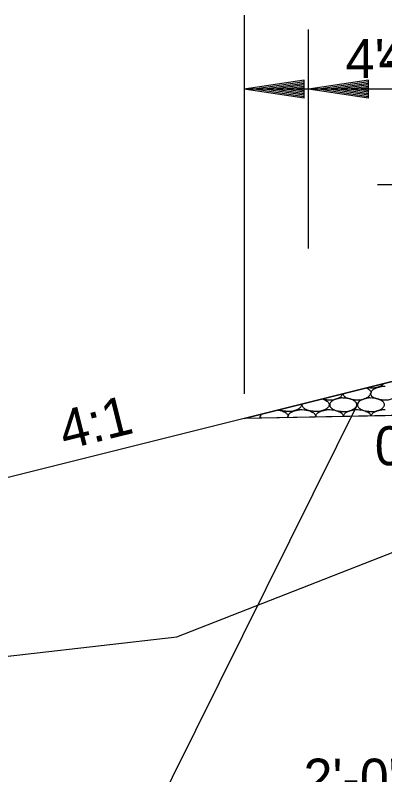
# Model space of a CAD drawing. Extents: x 1373719 to 1374161, y 379835 to 380167.
# Drawn here: x 1373940.76 to 1373946.92, y 380106.35 to 380119.01 of the extents above; entities that cross this region are included whole.
import ezdxf

# ---------------------------------------------------------------- set-up
doc = ezdxf.new("R2010")
doc.units = 0
for name, color, linetype in [('Agg Base Course Text', 7, 'Continuous'), ('Aggregate Base Course', 7, 'Continuous'), ('GREEN_TXT', 7, 'Continuous'), ('SIGNATURE', 7, 'Continuous'), ('T_Drafting', 7, 'Continuous'), ('Text 1', 7, 'Continuous')]:
    doc.layers.add(name, color=color, linetype=linetype)

msp = doc.modelspace()

# ---------------------------------------------------------------- linework, layer by layer
for p, q in [((1373950.023, 380113.65), (1373934.02, 380109.65)), ((1373955.044, 380112.497), (1373944.572, 380112.288))]:
    msp.add_line(p, q)
at = {"layer": 'Agg Base Course Text'}
msp.add_lwpolyline([(1373941.262, 380104.738), (1373942.599, 380104.738), (1373946.507, 380112.608)], dxfattribs=at)
at = {"layer": 'Aggregate Base Course'}
for points, degree in [([(1373946.609, 380112.797), (1373946.617, 380112.793), (1373946.625, 380112.789), (1373946.653, 380112.774), (1373946.669, 380112.76), (1373946.685, 380112.731), (1373946.686, 380112.722), (1373946.687, 380112.712), (1373946.687, 380112.712), (1373946.687, 380112.711)], 3), ([(1373946.894, 380112.868), (1373946.892, 380112.865), (1373946.89, 380112.862), (1373946.878, 380112.849), (1373946.87, 380112.843), (1373946.842, 380112.827), (1373946.824, 380112.818), (1373946.778, 380112.804), (1373946.753, 380112.797), (1373946.713, 380112.795), (1373946.7, 380112.795), (1373946.667, 380112.797), (1373946.647, 380112.799), (1373946.627, 380112.801), (1373946.627, 380112.801), (1373946.627, 380112.801)], 3), ([(1373946.692, 380112.711), (1373946.692, 380112.712), (1373946.692, 380112.712), (1373946.692, 380112.713), (1373946.693, 380112.728), (1373946.697, 380112.743), (1373946.707, 380112.756), (1373946.717, 380112.77), (1373946.729, 380112.778), (1373946.743, 380112.785), (1373946.755, 380112.791), (1373946.766, 380112.797), (1373946.779, 380112.801), (1373946.797, 380112.807), (1373946.815, 380112.813), (1373946.833, 380112.817), (1373946.844, 380112.82), (1373946.855, 380112.823), (1373946.867, 380112.825), (1373946.884, 380112.827), (1373946.901, 380112.828), (1373946.917, 380112.826)], 3), ([(1373946.917, 380112.826), (1373946.919, 380112.826), (1373946.921, 380112.827), (1373946.923, 380112.826)], 2), ([(1373946.215, 380112.698), (1373946.211, 380112.683), (1373946.201, 380112.67), (1373946.182, 380112.648), (1373946.173, 380112.641), (1373946.145, 380112.625), (1373946.127, 380112.617), (1373946.082, 380112.602), (1373946.056, 380112.595), (1373946.019, 380112.594), (1373946.007, 380112.594), (1373945.996, 380112.594)], 3), ([(1373946.457, 380112.594), (1373946.454, 380112.594), (1373946.452, 380112.594), (1373946.43, 380112.594), (1373946.41, 380112.596), (1373946.369, 380112.603), (1373946.349, 380112.61), (1373946.311, 380112.621), (1373946.294, 380112.626), (1373946.258, 380112.642), (1373946.242, 380112.656), (1373946.227, 380112.684), (1373946.225, 380112.692), (1373946.225, 380112.701)], 3), ([(1373946.676, 380112.711), (1373946.676, 380112.709), (1373946.676, 380112.708), (1373946.676, 380112.706), (1373946.676, 380112.688), (1373946.664, 380112.672), (1373946.651, 380112.657), (1373946.643, 380112.648), (1373946.634, 380112.641), (1373946.624, 380112.636), (1373946.606, 380112.625), (1373946.588, 380112.617), (1373946.568, 380112.61), (1373946.543, 380112.602), (1373946.517, 380112.595), (1373946.491, 380112.594), (1373946.479, 380112.594), (1373946.468, 380112.594), (1373946.457, 380112.594)], 3), ([(1373946.917, 380112.594), (1373946.915, 380112.594), (1373946.913, 380112.594), (1373946.91, 380112.594), (1373946.89, 380112.594), (1373946.871, 380112.596), (1373946.851, 380112.6), (1373946.83, 380112.603), (1373946.81, 380112.61), (1373946.789, 380112.616), (1373946.772, 380112.621), (1373946.755, 380112.626), (1373946.737, 380112.634), (1373946.718, 380112.642), (1373946.702, 380112.656), (1373946.692, 380112.675), (1373946.687, 380112.685), (1373946.685, 380112.695), (1373946.685, 380112.706), (1373946.685, 380112.708), (1373946.685, 380112.709), (1373946.685, 380112.711)], 3), ([(1373947.137, 380112.711), (1373947.137, 380112.709), (1373947.137, 380112.708), (1373947.136, 380112.688), (1373947.125, 380112.672), (1373947.104, 380112.648), (1373947.095, 380112.641), (1373947.067, 380112.625), (1373947.049, 380112.617), (1373947.003, 380112.602), (1373946.978, 380112.595), (1373946.94, 380112.594), (1373946.929, 380112.594), (1373946.917, 380112.594)], 3), ([(1373945.53, 380112.527), (1373945.53, 380112.524), (1373945.53, 380112.52), (1373945.527, 380112.5), (1373945.518, 380112.483), (1373945.496, 380112.459), (1373945.488, 380112.452), (1373945.459, 380112.436), (1373945.441, 380112.428), (1373945.396, 380112.413), (1373945.371, 380112.407), (1373945.331, 380112.404), (1373945.318, 380112.404), (1373945.285, 380112.407), (1373945.265, 380112.408), (1373945.223, 380112.413), (1373945.202, 380112.416), (1373945.17, 380112.424), (1373945.161, 380112.428), (1373945.152, 380112.433)], 3), ([(1373945.876, 380112.614), (1373945.896, 380112.608), (1373945.916, 380112.6), (1373945.956, 380112.578), (1373945.97, 380112.564), (1373945.989, 380112.535), (1373945.992, 380112.525), (1373945.987, 380112.5), (1373945.979, 380112.483), (1373945.957, 380112.459), (1373945.948, 380112.452), (1373945.92, 380112.436), (1373945.902, 380112.428), (1373945.857, 380112.413), (1373945.831, 380112.407), (1373945.792, 380112.404), (1373945.779, 380112.404), (1373945.746, 380112.407), (1373945.726, 380112.408), (1373945.684, 380112.413), (1373945.663, 380112.416), (1373945.624, 380112.426), (1373945.608, 380112.435), (1373945.575, 380112.456), (1373945.56, 380112.467), (1373945.541, 380112.496), (1373945.54, 380112.507), (1373945.541, 380112.521), (1373945.541, 380112.526), (1373945.542, 380112.53)], 3), ([(1373945.996, 380112.594), (1373945.993, 380112.594), (1373945.991, 380112.594), (1373945.969, 380112.594), (1373945.949, 380112.596), (1373945.911, 380112.603), (1373945.893, 380112.608), (1373945.875, 380112.613)], 3), ([(1373946.226, 380112.63), (1373946.253, 380112.631), (1373946.279, 380112.627), (1373946.305, 380112.621), (1373946.338, 380112.615), (1373946.367, 380112.605), (1373946.397, 380112.589), (1373946.417, 380112.578), (1373946.431, 380112.564), (1373946.444, 380112.544), (1373946.45, 380112.535), (1373946.453, 380112.525), (1373946.451, 380112.517), (1373946.448, 380112.5), (1373946.439, 380112.483), (1373946.426, 380112.468), (1373946.418, 380112.459), (1373946.409, 380112.452), (1373946.399, 380112.447), (1373946.381, 380112.436), (1373946.363, 380112.428), (1373946.343, 380112.421), (1373946.318, 380112.413), (1373946.292, 380112.407), (1373946.266, 380112.405), (1373946.253, 380112.404), (1373946.239, 380112.404), (1373946.226, 380112.405), (1373946.206, 380112.407), (1373946.187, 380112.408), (1373946.167, 380112.411), (1373946.145, 380112.413), (1373946.124, 380112.416), (1373946.102, 380112.421), (1373946.084, 380112.426), (1373946.069, 380112.435), (1373946.053, 380112.445), (1373946.036, 380112.456), (1373946.021, 380112.467), (1373946.008, 380112.486), (1373946.002, 380112.496), (1373946.001, 380112.507), (1373946.001, 380112.517), (1373946.002, 380112.531), (1373946.005, 380112.546), (1373946.016, 380112.56), (1373946.026, 380112.574), (1373946.038, 380112.582), (1373946.052, 380112.589), (1373946.063, 380112.595), (1373946.075, 380112.601), (1373946.088, 380112.605), (1373946.105, 380112.611), (1373946.123, 380112.616), (1373946.142, 380112.621), (1373946.153, 380112.624), (1373946.164, 380112.627), (1373946.176, 380112.628), (1373946.192, 380112.631), (1373946.21, 380112.632), (1373946.226, 380112.63)], 3), ([(1373946.687, 380112.63), (1373946.713, 380112.631), (1373946.74, 380112.627), (1373946.798, 380112.615), (1373946.828, 380112.605), (1373946.878, 380112.578), (1373946.892, 380112.564), (1373946.911, 380112.535), (1373946.914, 380112.525), (1373946.909, 380112.5), (1373946.9, 380112.483), (1373946.878, 380112.459), (1373946.87, 380112.452), (1373946.842, 380112.436), (1373946.824, 380112.428), (1373946.778, 380112.413), (1373946.753, 380112.407), (1373946.713, 380112.404), (1373946.7, 380112.404), (1373946.667, 380112.407), (1373946.647, 380112.408), (1373946.606, 380112.413), (1373946.584, 380112.416), (1373946.545, 380112.426), (1373946.53, 380112.435), (1373946.496, 380112.456), (1373946.482, 380112.467), (1373946.463, 380112.496), (1373946.461, 380112.507), (1373946.463, 380112.531), (1373946.466, 380112.546), (1373946.487, 380112.574), (1373946.499, 380112.582), (1373946.524, 380112.595), (1373946.536, 380112.601), (1373946.566, 380112.611), (1373946.584, 380112.616), (1373946.614, 380112.624), (1373946.625, 380112.627), (1373946.653, 380112.631), (1373946.67, 380112.632), (1373946.687, 380112.63)], 3), ([(1373945.142, 380112.43), (1373945.147, 380112.429), (1373945.153, 380112.428), (1373945.191, 380112.42), (1373945.221, 380112.41), (1373945.271, 380112.384), (1373945.286, 380112.37), (1373945.302, 380112.341), (1373945.304, 380112.332), (1373945.305, 380112.322), (1373945.305, 380112.321), (1373945.305, 380112.321)], 3), ([(1373945.31, 380112.321), (1373945.31, 380112.321), (1373945.31, 380112.322), (1373945.31, 380112.322), (1373945.31, 380112.338), (1373945.315, 380112.352), (1373945.324, 380112.366), (1373945.334, 380112.379), (1373945.347, 380112.387), (1373945.36, 380112.394), (1373945.372, 380112.401), (1373945.384, 380112.406), (1373945.396, 380112.411), (1373945.414, 380112.417), (1373945.432, 380112.422), (1373945.45, 380112.427), (1373945.462, 380112.43), (1373945.473, 380112.432), (1373945.485, 380112.434), (1373945.501, 380112.437), (1373945.518, 380112.437), (1373945.535, 380112.436)], 3), ([(1373945.535, 380112.436), (1373945.537, 380112.436), (1373945.539, 380112.436), (1373945.54, 380112.436)], 2), ([(1373945.54, 380112.436), (1373945.567, 380112.436), (1373945.593, 380112.432), (1373945.62, 380112.427), (1373945.652, 380112.42), (1373945.682, 380112.41), (1373945.711, 380112.394), (1373945.731, 380112.384), (1373945.747, 380112.37), (1373945.758, 380112.349), (1373945.763, 380112.341), (1373945.765, 380112.332), (1373945.765, 380112.322), (1373945.765, 380112.322), (1373945.766, 380112.321), (1373945.765, 380112.321)], 3), ([(1373945.771, 380112.321), (1373945.771, 380112.321), (1373945.771, 380112.322), (1373945.771, 380112.322), (1373945.771, 380112.338), (1373945.775, 380112.352), (1373945.785, 380112.366), (1373945.795, 380112.379), (1373945.807, 380112.387), (1373945.821, 380112.394), (1373945.833, 380112.401), (1373945.845, 380112.406), (1373945.857, 380112.411), (1373945.875, 380112.417), (1373945.893, 380112.422), (1373945.911, 380112.427), (1373945.923, 380112.43), (1373945.934, 380112.432), (1373945.945, 380112.434), (1373945.962, 380112.437), (1373945.979, 380112.437), (1373945.996, 380112.436)], 3), ([(1373945.996, 380112.436), (1373945.998, 380112.436), (1373945.999, 380112.436), (1373946.001, 380112.436)], 2), ([(1373946.001, 380112.436), (1373946.028, 380112.436), (1373946.054, 380112.432), (1373946.113, 380112.42), (1373946.142, 380112.41), (1373946.192, 380112.384), (1373946.208, 380112.37), (1373946.224, 380112.341), (1373946.225, 380112.332), (1373946.226, 380112.322), (1373946.226, 380112.321), (1373946.226, 380112.321)], 3), ([(1373946.232, 380112.321), (1373946.232, 380112.321), (1373946.232, 380112.322), (1373946.232, 380112.338), (1373946.236, 380112.352), (1373946.256, 380112.379), (1373946.268, 380112.387), (1373946.294, 380112.401), (1373946.305, 380112.406), (1373946.336, 380112.417), (1373946.354, 380112.422), (1373946.383, 380112.43), (1373946.395, 380112.432), (1373946.423, 380112.437), (1373946.44, 380112.437), (1373946.457, 380112.436)], 3), ([(1373946.457, 380112.436), (1373946.458, 380112.436), (1373946.46, 380112.436), (1373946.462, 380112.436)], 2), ([(1373946.462, 380112.436), (1373946.488, 380112.436), (1373946.515, 380112.432), (1373946.573, 380112.42), (1373946.603, 380112.41), (1373946.653, 380112.384), (1373946.669, 380112.37), (1373946.683, 380112.343), (1373946.685, 380112.337), (1373946.686, 380112.33)], 3), ([(1373946.693, 380112.33), (1373946.694, 380112.343), (1373946.699, 380112.354), (1373946.717, 380112.379), (1373946.729, 380112.387), (1373946.755, 380112.401), (1373946.766, 380112.406), (1373946.797, 380112.417), (1373946.815, 380112.422), (1373946.844, 380112.43), (1373946.855, 380112.432), (1373946.884, 380112.437), (1373946.901, 380112.437), (1373946.917, 380112.436)], 3), ([(1373946.917, 380112.436), (1373946.919, 380112.436), (1373946.921, 380112.436), (1373946.923, 380112.436)], 2), ([(1373944.833, 380112.321), (1373944.833, 380112.319), (1373944.833, 380112.317), (1373944.833, 380112.307), (1373944.83, 380112.3), (1373944.827, 380112.293)], 3), ([(1373944.834, 380112.353), (1373944.835, 380112.352), (1373944.836, 380112.351), (1373944.841, 380112.341), (1373944.843, 380112.332), (1373944.844, 380112.322), (1373944.844, 380112.321), (1373944.844, 380112.321)], 3), ([(1373944.846, 380112.293), (1373944.843, 380112.3), (1373944.842, 380112.308), (1373944.842, 380112.317), (1373944.842, 380112.319), (1373944.842, 380112.321)], 3), ([(1373944.849, 380112.321), (1373944.849, 380112.321), (1373944.849, 380112.322), (1373944.849, 380112.335), (1373944.853, 380112.348), (1373944.86, 380112.36)], 3), ([(1373945.294, 380112.321), (1373945.294, 380112.319), (1373945.294, 380112.317), (1373945.294, 380112.311), (1373945.293, 380112.306), (1373945.291, 380112.302)], 3), ([(1373945.304, 380112.302), (1373945.303, 380112.307), (1373945.303, 380112.311), (1373945.303, 380112.317), (1373945.303, 380112.319), (1373945.303, 380112.321)], 3), ([(1373945.755, 380112.321), (1373945.755, 380112.319), (1373945.755, 380112.317), (1373945.755, 380112.314), (1373945.754, 380112.313), (1373945.754, 380112.311)], 3), ([(1373945.764, 380112.312), (1373945.764, 380112.313), (1373945.764, 380112.314), (1373945.764, 380112.317), (1373945.764, 380112.319), (1373945.764, 380112.321)], 3), ([(1373946.215, 380112.321), (1373946.215, 380112.321), (1373946.215, 380112.321), (1373946.215, 380112.321)], 2)]:
    msp.add_open_spline(points, degree=degree, dxfattribs=at)
at = {"layer": 'GREEN_TXT'}
for p, q in [((1373944.572, 380119.007), (1373944.572, 380112.699)), ((1373945.572, 380117.922), (1373944.572, 380117.772)), ((1373945.572, 380117.897), (1373944.739, 380117.772)), ((1373945.572, 380117.871), (1373944.911, 380117.772)), ((1373945.572, 380117.846), (1373945.078, 380117.772)), ((1373945.572, 380117.821), (1373945.247, 380117.772)), ((1373945.572, 380117.622), (1373945.572, 380117.922)), ((1373945.572, 380117.622), (1373944.572, 380117.772)), ((1373950.02, 380117.772), (1373944.572, 380117.772)), ((1373945.572, 380117.647), (1373944.739, 380117.772)), ((1373945.572, 380117.672), (1373944.911, 380117.772)), ((1373945.572, 380117.697), (1373945.078, 380117.772)), ((1373945.572, 380117.723), (1373945.247, 380117.772)), ((1373945.572, 380117.795), (1373945.414, 380117.772)), ((1373945.572, 380117.748), (1373945.414, 380117.772))]:
    msp.add_line(p, q, dxfattribs=at)
at = {"layer": 'SIGNATURE'}
msp.add_lwpolyline([(1373944.572, 380112.288), (1373948.15, 380113.182), (1373950.023, 380113.65), (1373950.28, 380113.661), (1373950.02, 380113.4), (1373951.01, 380113.439), (1373951.388, 380112.424), (1373950.021, 380112.397)], close=True, dxfattribs=at)
at = {"layer": 'T_Drafting'}
msp.add_lwpolyline([(1373907.987, 380106.564), (1373924.533, 380106.487), (1373943.45, 380108.654), (1373953.585, 380112.614), (1373955.026, 380112.615), (1373964.851, 380112.903), (1373975.028, 380112.689), (1373976.603, 380112.615), (1373985.688, 380110.353), (1373993.989, 380112.909), (1374008.917, 380113.95), (1374025.023, 380113.95)], dxfattribs=at)
at = {"layer": 'Text 1'}
for p, q in [((1373945.645, 380115.12), (1373945.645, 380118.768)), ((1373946.645, 380117.922), (1373945.645, 380117.772)), ((1373946.645, 380117.897), (1373945.812, 380117.772)), ((1373946.645, 380117.871), (1373945.984, 380117.772)), ((1373946.645, 380117.846), (1373946.151, 380117.772)), ((1373946.645, 380117.821), (1373946.32, 380117.772)), ((1373946.645, 380117.622), (1373946.645, 380117.922)), ((1373949.895, 380117.772), (1373945.645, 380117.772)), ((1373946.645, 380117.622), (1373945.645, 380117.772)), ((1373946.645, 380117.647), (1373945.812, 380117.772)), ((1373946.645, 380117.672), (1373945.984, 380117.772)), ((1373946.645, 380117.697), (1373946.151, 380117.772)), ((1373946.645, 380117.723), (1373946.32, 380117.772)), ((1373946.645, 380117.795), (1373946.487, 380117.772)), ((1373946.645, 380117.748), (1373946.487, 380117.772)), ((1373952.02, 380116.18), (1373946.797, 380116.18))]:
    msp.add_line(p, q, dxfattribs=at)

# ---------------------------------------------------------------- texts
at = {"layer": 'Agg Base Course Text'}
msp.add_text('2\'-0" AGGREGATE BASE CRSE. (CL. 7)', height=0.65, dxfattribs=at).set_placement((1373945.562, 380105.973))
at = {"layer": 'GREEN_TXT'}
msp.add_text('4\'-3"', height=0.65, dxfattribs=at).set_placement((1373946.264, 380117.958))
for s, rotation, p in [('4:1', 13.9941, (1373941.586, 380111.762)), ("0.02'/'", 359.98, (1373946.75, 380111.51))]:
    msp.add_text(s, height=0.65, rotation=rotation, dxfattribs=at).set_placement(p)
at = {"layer": 'Text 1'}
msp.add_text('4\'-6"', height=0.65, dxfattribs=at).set_placement((1373946.809, 380117.992))

doc.saveas('drawing.dxf')
